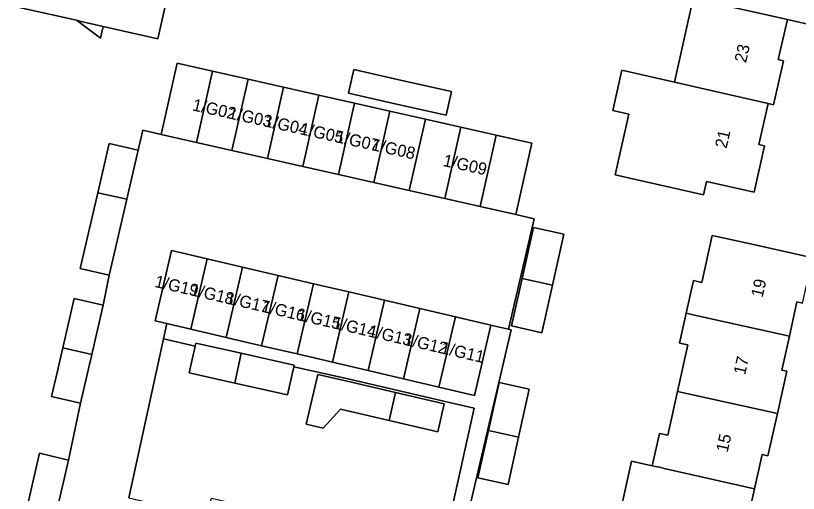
# Model space of a CAD drawing. Extents: x 161771 to 163125, y 382475 to 383179.
# Drawn here: x 162499.5 to 162564.1, y 382638.4 to 382677.9 of the extents above; entities that cross this region are included whole.
import ezdxf

# ---------------------------------------------------------------- set-up
doc = ezdxf.new("R2010")
doc.units = 0
for name, color, linetype in [('IMGEO_Erf', 7, 'Continuous'), ('IMGEO_Pand', 7, 'Continuous'), ('IMGEO_Pand_nummerreeks', 7, 'Continuous'), ('IMGEO_Rijbaan_lokaal_open', 7, 'Continuous'), ('IMGEO_Voetpad_open', 7, 'Continuous')]:
    doc.layers.add(name, color=color, linetype=linetype)

msp = doc.modelspace()

# ---------------------------------------------------------------- linework, layer by layer
at = {"layer": 'IMGEO_Erf'}
for points in [[(162512.697, 382682.596), (162511.203, 382675.995), (162506.674, 382677.02), (162506.454, 382676.051), (162504.466, 382677.52), (162500, 382678.532)], [(162566.689, 382681.489), (162566.846, 382676.771), (162563.22, 382677.59), (162562.469, 382674.269), (162562.89, 382674.174), (162562.07, 382670.542), (162561.622, 382670.635), (162560.855, 382667.242), (162561.335, 382667.134), (162560.47, 382663.309), (162556.53, 382664.2), (162556.279, 382663.089), (162551.402, 382664.191), (162548.983, 382664.738), (162550.121, 382669.772), (162548.795, 382670.072), (162549.545, 382673.389), (162553.879, 382672.41), (162555.446, 382679.346)], [(162500.473, 382637.637), (162501.417, 382641.716), (162503.813, 382641.161), (162504.805, 382645.86), (162502.869, 382646.308), (162502.409, 382646.415), (162502.869, 382648.402), (162503.342, 382650.442), (162504.286, 382654.521), (162506.682, 382653.966), (162507.177, 382656.448), (162504.782, 382657.003), (162506.23, 382663.256), (162507.174, 382667.335), (162509.57, 382666.78), (162509.952, 382668.431), (162511.464, 382668.081), (162512.792, 382673.966), (162515.723, 382673.305), (162518.654, 382672.644), (162521.584, 382671.983), (162524.515, 382671.322), (162527.446, 382670.662), (162530.377, 382670.001), (162533.308, 382669.34), (162536.238, 382668.679), (162539.169, 382668.018), (162542.1, 382667.357), (162540.772, 382661.472), (162542.309, 382661.113), (162540.176, 382651.979), (162540.384, 382651.93), (162536.453, 382635.087)], [(162548.928, 382634.68), (162550.35, 382641.08), (162552.054, 382640.692), (162552.078, 382640.798), (162552.647, 382643.36), (162553.343, 382643.206), (162554.149, 382646.832), (162555.004, 382650.682), (162554.308, 382650.836), (162554.857, 382653.305), (162555.456, 382655.999), (162556.152, 382655.844), (162557.016, 382659.734), (162560.432, 382658.975), (162565.313, 382657.891)], [(162564.476, 382654.127), (162564.008, 382654.231), (162563.381, 382651.41), (162562.755, 382648.589), (162563.17, 382648.497), (162562.393, 382644.999), (162561.615, 382641.501), (162561.125, 382641.61), (162560.495, 382638.773), (162559.867, 382635.947)]]:
    msp.add_lwpolyline(points, dxfattribs=at)
for points in [[(162535.033, 382669.672), (162530.933, 382670.597), (162526.949, 382671.496), (162527.39, 382673.449), (162531.374, 382672.551), (162535.474, 382671.626)], [(162543.799, 382655.611), (162542.928, 382651.692), (162540.433, 382652.247), (162541.304, 382656.165), (162542.244, 382660.394), (162544.738, 382659.839)], [(162537.348, 382645.451), (162535.3, 382645.93), (162526.78, 382647.894), (162522.428, 382648.868), (162521.91, 382646.554), (162517.55, 382647.531), (162513.778, 382648.375), (162514.272, 382650.581), (162511.664, 382651.185), (162508.801, 382638.039), (162515.192, 382636.56), (162515.281, 382636.539), (162515.624, 382638.019), (162522, 382636.543), (162521.683, 382635.2), (162527.882, 382633.765), (162527.297, 382631.051), (162533.808, 382629.543)], [(162526.297, 382645.377), (162524.859, 382643.792), (162523.455, 382644.12), (162524.415, 382648.235), (162526.832, 382647.671), (162530.847, 382646.734), (162534.862, 382645.797), (162534.327, 382643.503), (162530.312, 382644.44)], [(162541.007, 382643.05), (162540.135, 382639.126), (162537.64, 382639.681), (162538.514, 382643.617), (162539.397, 382647.586), (162541.892, 382647.031)]]:
    msp.add_lwpolyline(points, close=True, dxfattribs=at)
at = {"layer": 'IMGEO_Pand'}
for points in [[(162564.755, 382684.377), (162566.606, 382683.958), (162566.596, 382684.237), (162565.267, 382684.527), (162565.348, 382684.887), (162560.472, 382685.989), (162557.119, 382686.747), (162552.561, 382687.778), (162552.901, 382679.921), (162555.446, 382679.346), (162563.22, 382677.59), (162566.846, 382676.771), (162566.689, 382681.489), (162564.262, 382682.193)], [(162512.697, 382682.596), (162512.58, 382682.623), (162509.083, 382683.414), (162500.915, 382685.195), (162500.881, 382685.046), (162501.351, 382684.94), (162500.753, 382682.282), (162500.283, 382682.388), (162500, 382681.117), (162499.452, 382678.656), (162500, 382678.532), (162504.466, 382677.52), (162504.877, 382677.427), (162506.674, 382677.02), (162511.203, 382675.995)], [(162563.22, 382677.59), (162555.446, 382679.346), (162553.879, 382672.41), (162561.622, 382670.635), (162562.07, 382670.542), (162562.89, 382674.174), (162562.469, 382674.269)], [(162506.674, 382677.02), (162504.877, 382677.427), (162504.466, 382677.52), (162506.454, 382676.051)], [(162514.396, 382667.42), (162515.723, 382673.305), (162512.792, 382673.966), (162511.464, 382668.081)], [(162514.396, 382667.42), (162517.326, 382666.759), (162518.654, 382672.644), (162515.723, 382673.305)], [(162535.474, 382671.626), (162531.374, 382672.551), (162527.39, 382673.449), (162526.949, 382671.496), (162530.933, 382670.597), (162535.033, 382669.672)], [(162561.622, 382670.635), (162553.879, 382672.41), (162549.545, 382673.389), (162548.795, 382670.072), (162550.121, 382669.772), (162548.983, 382664.738), (162551.402, 382664.191), (162556.279, 382663.089), (162556.53, 382664.2), (162560.47, 382663.309), (162561.335, 382667.134), (162560.855, 382667.242)], [(162518.654, 382672.644), (162517.326, 382666.759), (162520.257, 382666.098), (162521.584, 382671.983)], [(162520.257, 382666.098), (162523.188, 382665.437), (162524.515, 382671.322), (162521.584, 382671.983)], [(162526.119, 382664.776), (162527.446, 382670.662), (162524.515, 382671.322), (162523.188, 382665.437)], [(162526.119, 382664.776), (162529.05, 382664.115), (162530.377, 382670.001), (162527.446, 382670.662)], [(162533.308, 382669.34), (162530.377, 382670.001), (162529.05, 382664.115), (162531.98, 382663.455)], [(162533.308, 382669.34), (162531.98, 382663.455), (162534.911, 382662.794), (162536.238, 382668.679)], [(162539.169, 382668.018), (162536.238, 382668.679), (162534.911, 382662.794), (162537.842, 382662.133)], [(162539.169, 382668.018), (162537.842, 382662.133), (162540.772, 382661.472), (162542.1, 382667.357)], [(162506.23, 382663.256), (162508.634, 382662.737), (162509.57, 382666.78), (162507.174, 382667.335)], [(162508.634, 382662.737), (162506.23, 382663.256), (162504.782, 382657.003), (162507.177, 382656.448), (162507.693, 382658.674)], [(162541.304, 382656.165), (162543.799, 382655.611), (162544.738, 382659.839), (162542.244, 382660.394)], [(162565.313, 382657.891), (162560.432, 382658.975), (162557.016, 382659.734), (162556.152, 382655.844), (162555.456, 382655.999), (162554.857, 382653.305), (162555.553, 382653.15), (162563.381, 382651.41), (162564.008, 382654.231), (162564.476, 382654.127)], [(162512.341, 382658.481), (162510.984, 382652.67), (162511.955, 382652.443), (162513.914, 382651.986), (162515.271, 382657.796)], [(162513.914, 382651.986), (162516.845, 382651.301), (162518.202, 382657.112), (162515.271, 382657.796)], [(162518.202, 382657.112), (162516.845, 382651.301), (162519.775, 382650.617), (162521.132, 382656.427)], [(162524.063, 382655.743), (162521.132, 382656.427), (162519.775, 382650.617), (162522.705, 382649.932)], [(162543.799, 382655.611), (162541.304, 382656.165), (162540.433, 382652.247), (162542.928, 382651.692)], [(162524.063, 382655.743), (162522.705, 382649.932), (162525.636, 382649.248), (162526.993, 382655.058)], [(162526.993, 382655.058), (162525.636, 382649.248), (162528.566, 382648.563), (162529.924, 382654.374)], [(162505.737, 382649.88), (162506.682, 382653.966), (162504.286, 382654.521), (162503.342, 382650.442)], [(162532.854, 382653.689), (162529.924, 382654.374), (162528.566, 382648.563), (162531.497, 382647.879)], [(162532.854, 382653.689), (162531.497, 382647.879), (162534.427, 382647.194), (162535.785, 382653.005)], [(162534.427, 382647.194), (162537.358, 382646.51), (162538.715, 382652.32), (162535.785, 382653.005)], [(162563.381, 382651.41), (162555.553, 382653.15), (162554.857, 382653.305), (162554.308, 382650.836), (162555.004, 382650.682), (162554.149, 382646.832), (162562.393, 382644.999), (162563.17, 382648.497), (162562.755, 382648.589)], [(162505.737, 382649.88), (162503.342, 382650.442), (162502.869, 382648.402), (162502.409, 382646.415), (162502.869, 382646.308), (162504.805, 382645.86)], [(162518.093, 382649.985), (162514.327, 382650.828), (162514.272, 382650.581), (162513.778, 382648.375), (162517.55, 382647.531)], [(162522.428, 382648.868), (162522.459, 382649.007), (162518.093, 382649.985), (162517.55, 382647.531), (162521.91, 382646.554)], [(162530.847, 382646.734), (162526.832, 382647.671), (162524.415, 382648.235), (162523.455, 382644.12), (162524.859, 382643.792), (162526.297, 382645.377), (162530.312, 382644.44)], [(162538.514, 382643.617), (162541.007, 382643.05), (162541.892, 382647.031), (162539.397, 382647.586)], [(162530.847, 382646.734), (162530.312, 382644.44), (162534.327, 382643.503), (162534.862, 382645.797)], [(162562.393, 382644.999), (162554.149, 382646.832), (162553.343, 382643.206), (162552.647, 382643.36), (162552.078, 382640.798), (162552.054, 382640.692), (162552.75, 382640.534), (162553.038, 382640.469), (162560.495, 382638.773), (162561.125, 382641.61), (162561.615, 382641.501)], [(162541.007, 382643.05), (162538.514, 382643.617), (162537.64, 382639.681), (162540.135, 382639.126)], [(162500.473, 382637.637), (162502.872, 382637.096), (162503.813, 382641.161), (162501.417, 382641.716)], [(162560.495, 382638.773), (162553.038, 382640.469), (162552.75, 382640.534), (162552.054, 382640.692), (162550.35, 382641.08), (162548.928, 382634.68), (162551.337, 382634.178), (162551.746, 382634.093), (162559.426, 382632.343), (162560.21, 382635.87), (162559.867, 382635.947)]]:
    msp.add_lwpolyline(points, close=True, dxfattribs=at)
at = {"layer": 'IMGEO_Rijbaan_lokaal_open'}
msp.add_lwpolyline([(162508.801, 382638.039), (162511.664, 382651.185), (162511.955, 382652.443), (162510.984, 382652.67), (162512.341, 382658.481), (162515.271, 382657.796), (162518.202, 382657.112), (162521.132, 382656.427), (162524.063, 382655.743), (162526.993, 382655.058), (162529.924, 382654.374), (162532.854, 382653.689), (162535.785, 382653.005), (162538.715, 382652.32), (162538.941, 382652.267), (162540.176, 382651.979), (162542.309, 382661.113), (162540.772, 382661.472), (162537.842, 382662.133), (162534.911, 382662.794), (162531.98, 382663.455), (162529.05, 382664.115), (162526.119, 382664.776), (162523.188, 382665.437), (162520.257, 382666.098), (162517.326, 382666.759), (162514.396, 382667.42), (162511.464, 382668.081), (162509.952, 382668.431), (162509.57, 382666.78), (162508.634, 382662.737), (162507.693, 382658.674), (162507.177, 382656.448), (162506.682, 382653.966), (162505.737, 382649.88), (162504.805, 382645.86), (162503.813, 382641.161), (162502.872, 382637.096)], dxfattribs=at)
at = {"layer": 'IMGEO_Voetpad_open'}
msp.add_lwpolyline([(162536.453, 382635.087), (162540.384, 382651.93), (162540.176, 382651.979), (162538.941, 382652.267), (162538.715, 382652.32), (162537.358, 382646.51), (162534.427, 382647.194), (162531.497, 382647.879), (162528.566, 382648.563), (162525.636, 382649.248), (162522.705, 382649.932), (162519.775, 382650.617), (162516.845, 382651.301), (162513.914, 382651.986), (162511.955, 382652.443), (162511.664, 382651.185), (162514.272, 382650.581), (162514.327, 382650.828), (162518.093, 382649.985), (162522.459, 382649.007), (162522.428, 382648.868), (162526.78, 382647.894), (162535.3, 382645.93), (162537.348, 382645.451), (162533.808, 382629.543)], dxfattribs=at)

# ---------------------------------------------------------------- texts
at = {"layer": 'IMGEO_Pand_nummerreeks'}
for s, rotation, p in [('23', 77.1946, (162559.801, 382673.956)), ('1/G02', 347.49256, (162513.995, 382670.081)), ('1/G03', 347.49256, (162516.96, 382669.423)), ('1/G04', 347.49256, (162519.918, 382668.767)), ('1/G05', 347.49256, (162522.876, 382668.111)), ('1/G07', 347.49256, (162525.835, 382667.455)), ('1/G08', 347.49256, (162528.793, 382666.798)), ('21', 77.19571, (162558.192, 382666.876)), ('1/G09', 347.49256, (162534.707, 382665.487)), ('1/G19', 346.92304, (162510.879, 382655.487)), ('19', 77.28628, (162561.168, 382654.553)), ('1/G18', 346.92304, (162513.825, 382654.802)), ('1/G17', 346.92304, (162516.761, 382654.12)), ('1/G16', 346.92304, (162519.701, 382653.437)), ('1/G15', 346.92304, (162522.641, 382652.754)), ('1/G14', 346.92304, (162525.581, 382652.072)), ('1/G13', 346.92304, (162528.521, 382651.389)), ('1/G12', 346.92304, (162531.454, 382650.707)), ('1/G11', 346.92304, (162534.508, 382649.998)), ('17', 77.28628, (162559.723, 382648.151)), ('15', 77.28628, (162558.279, 382641.748))]:
    msp.add_text(s, height=1, rotation=rotation, dxfattribs=at).set_placement(p)

doc.saveas('drawing.dxf')
